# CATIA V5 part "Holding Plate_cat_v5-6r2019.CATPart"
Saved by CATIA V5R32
Part number: Holding Plate
Bounding box of the stored display mesh (mm): x -16 to 16, y -16 to 16, z 0 to 7
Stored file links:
  D:\PROJECTS\Project 2022\CATIA V5 6R 2022\Resources\Tutorial Files\c16_catia_v5_6r2022_tut\Bench vice\Holding Plate_cat_v5-6r2019.CATPart
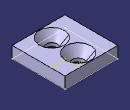
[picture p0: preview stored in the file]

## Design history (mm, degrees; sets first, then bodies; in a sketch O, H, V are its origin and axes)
Body1 (main body)
  Sketch1 on xy-plane, origin (0, 0, 0), H (1, 0, 0), V (0, 1, 0)
    line L1 (-16, 16) -> (16, 16)
    line L2 (16, 16) -> (16, -16)
    line L3 (16, -16) -> (-16, -16)
    line L4 (-16, -16) -> (-16, 16)
    construction line L5 (-16, 16) -> (16, -16)
    length L2 = 32
    length L3 = 32
    distance H L3 = 16
    distance V L4 = 16
    horizontal: L1 H, L3 H
    vertical: L2 V, L4 V
  Pad1: profile Sketch1, direction (0, 0, 1), length 7
  Sketch2 on face of Pad1, origin (-0.9262, 8.6399, 7), H (1, 0, 0), V (0, 1, 0)
    point P1 (0.9262, -0.6399)
    reference intersected line E1 through (0.9262, 0) direction (0, 1) from yz-plane
    reference projected line E3 (-15.0738, 7.3601) -> (16.9262, 7.3601) from edge of Pad1
    distance P1 E3 = 8
    coincidence: E1 P1
  Hole1: placed by Sketch2, at (0, 8, 7) direction (0, 0, -1), diameter 7, depth 10, countersink depth 5, countersink angle 80
  Mirror1: of Hole1, about zx-plane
